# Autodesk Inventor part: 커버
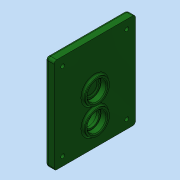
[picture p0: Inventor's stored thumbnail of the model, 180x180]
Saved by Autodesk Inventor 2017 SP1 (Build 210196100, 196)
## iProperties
Created: 2016-02
Part Number: 커버
Material: 일반
Document SubType Name: Modeling
Designer: mduedu
Density: 1 g/cm^3
Appearance: 매끄러움 - 짙은 산림 녹색
Author: mduedu
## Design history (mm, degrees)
sketch "스케치1"
  geometry: L1 (63, 47)-(-47, 47); L2 (-47, 47)-(-47, -47); L3 (-47, -47)-(63, -47); L4 (63, -47)-(63, 47); 2 further points
  constraints: 8 end point, 2 parallel, 1 horizontal, 1 horizontal alignment, 1 midpoint, 1 perpendicular
  dimensions: "d102" = 94 distance of L3.end L1.start; "d104" = 47 distance from line of L2 point (0, 0); "d105" = 110 distance of L1.start L1.end
extrude "돌출1" new body sketch "스케치1" distance "d1" = 10; taper "d2" = 0 deg
sketch "스케치2"
  geometry: C1 r 14 at (0, 11); 1 further point
  constraints: 1 centre point, 1 vertical alignment
  dimensions: "d3" = 28 diameter of C1; "d6" = 11 distance of C1.centre point (0, 0)
extrude "돌출2" join sketch "스케치2" distance "d7" = 3; taper "d8" = 0 deg
sketch "스케치3"
  geometry: C1 r 14 at (0, -20); 1 further point
  constraints: 1 centre point, 1 vertical alignment
  dimensions: "d9" = 28 diameter of C1; "d10" = 20 distance of C1.centre point (0, 0)
extrude "돌출3" join sketch "스케치3" distance "d11" = 3; taper "d12" = 0 deg
hole "구멍1" diameter "d15" = 22; stored, may be unused: countersink angle "d19" = 90 deg, drill point angle "d21" = 0 deg; dims "d13" = 10, "d14" = 10, "d16" = 6, "d17" = 4, "d18" = 2, "d20" = 7
hole "구멍2" diameter "d24" = 18; stored, may be unused: countersink angle "d28" = 90 deg, drill point angle "d30" = 0 deg; dims "d22" = 10, "d23" = 10, "d25" = 6, "d26" = 4, "d27" = 2, "d29" = 1
hole "구멍3" diameter "d33" = 22; stored, may be unused: countersink angle "d37" = 90 deg, drill point angle "d39" = 0 deg; dims "d34" = 6, "d35" = 4, "d36" = 2, "d38" = 7, "d73" = 10, "d74" = 10
sketch "스케치4"
  geometry: C1 r 14 at (0, -20) reference; C2 r 18 at (0, -20); 1 further point
  constraints: 1 centre point, 1 coincident
  dimensions: "d40" = 36 diameter of C2
extrude "돌출4" join sketch "스케치4" distance "d41" = 4; taper "d42" = 0 deg
hole "구멍4" diameter "d45" = 22; stored, may be unused: countersink angle "d49" = 90 deg, drill point angle "d51" = 0 deg; dims "d43" = 10, "d44" = 10, "d46" = 6, "d47" = 4, "d48" = 2, "d50" = 7
hole "구멍5" diameter "d54" = 18; stored, may be unused: countersink angle "d58" = 90 deg, drill point angle "d60" = 0 deg; dims "d55" = 6, "d56" = 4, "d57" = 2, "d59" = 7, "d116" = 10, "d117" = 10
fillet "모깎기1" dims "d61" = 0.3
fillet "모깎기2" dims "d62" = 2
chamfer "모따기1" distance "d63" = 1; stored, may be unused: second distance "d64" = 2, angle "d65" = 45 deg
fillet "모깎기6" dims "d88" = 2
fillet "모깎기4" dims "d75" = 2
sketch "스케치9"
  geometry: L1 (47, 63)-(47, -47) reference; L2 (-47, 63)-(47, 63) reference; L3 (-47, -47)-(-47, 63) reference; L4 (47, -47)-(-47, -47) reference; L5 (37, 53)-(37, -37); L6 (37, -37)-(-37, -37); L7 (-37, -37)-(-37, 53); L8 (-37, 53)-(37, 53); C1 r 20 at (0, -20) reference; 5 further points
  constraints: 8 end point, 4 coincident, 3 other
  dimensions: "d107" = 10 distance between parallel lines of L8 L2
hole "구멍7" sketch "스케치9" at (-37, 53), (37, 53), (37, -37), (-37, -37) diameter "d108" = 4.5; stored, may be unused: countersink angle "d112" = 90 deg, drill point angle "d114" = 118 deg; dims "d109" = 6, "d110" = 8, "d111" = 4.6, "d113" = 8
fillet "모깎기8" dims "d106" = 3
fillet "모깎기9" dims "d115" = 3
node "솔리드1"
node "투영된 루프2"
